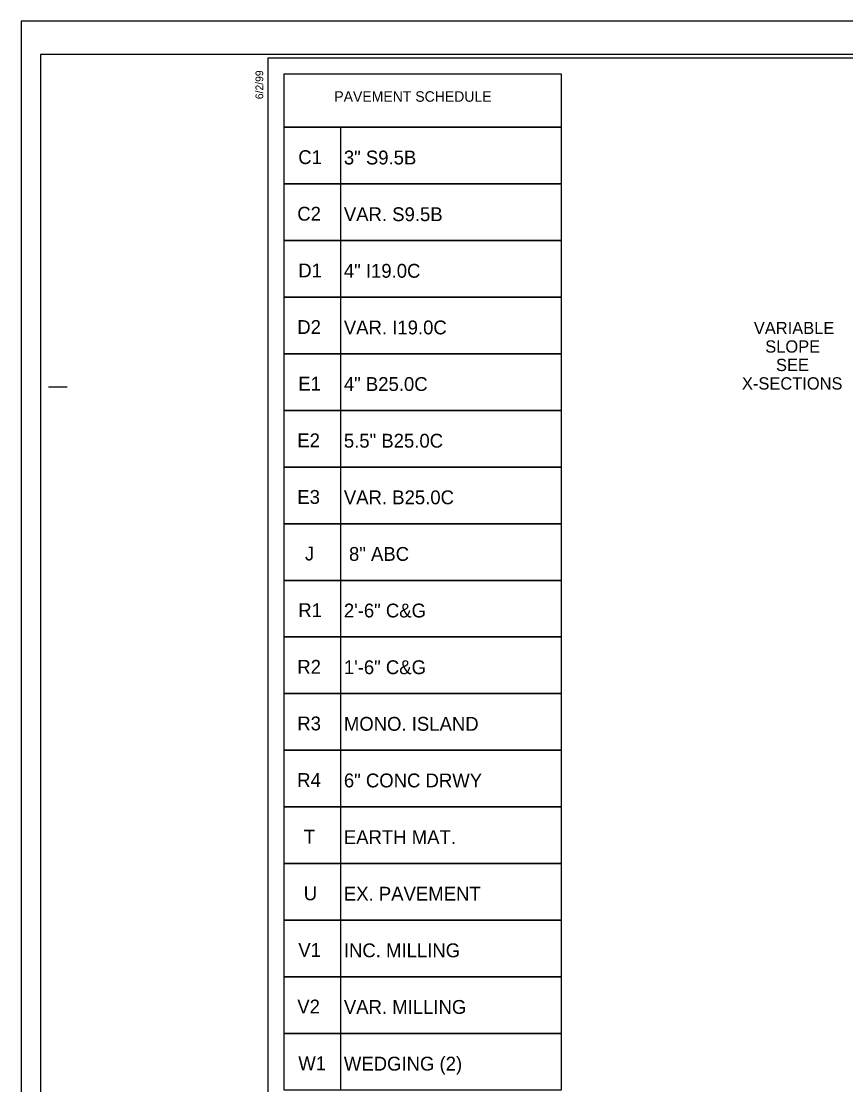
# Model space of a CAD drawing. Extents: x 3025871 to 3026431, y 707165 to 707825.
# Drawn here: x 3026022 to 3026105.8, y 707279.4 to 707387.4 of the extents above; entities that cross this region are included whole.
import ezdxf

# ---------------------------------------------------------------- set-up
doc = ezdxf.new("R2010")
doc.units = 0
for name, color, linetype in [('Default', 7, 'Continuous'), ('Old_Level_39', 7, 'Continuous'), ('Prop Drainage Structure Junction Box with Slab Lid TB 840 34 CELL', 7, 'Continuous'), ('Sheet Cutting Line CELL', 7, 'Continuous'), ('Typical ID Circle CELL', 7, 'Continuous'), ('Typical Terminator CELL', 7, 'Continuous')]:
    doc.layers.add(name, color=color, linetype=linetype)

msp = doc.modelspace()

# ---------------------------------------------------------------- linework, layer by layer
at = {"layer": 'Default'}
msp.add_lwpolyline([(3026048.72, 707382.05), (3026076.85, 707382.05), (3026076.85, 707376.61), (3026048.72, 707376.61)], close=True, dxfattribs=at)
at = {"layer": 'Old_Level_39'}
msp.add_lwpolyline([(3026273.95, 707384.02), (3026023.97, 707384.02), (3026023.97, 707225.75), (3026273.95, 707225.75)], close=True, dxfattribs=at)
at = {"layer": 'Sheet Cutting Line CELL'}
msp.add_line((3026024.8, 707350.26), (3026026.67, 707350.26), dxfattribs=at)
msp.add_lwpolyline([(3026272.07, 707383.63), (3026047.07, 707383.63), (3026047.07, 707226.13), (3026272.07, 707226.13)], close=True, dxfattribs=at)
at = {"layer": 'Typical ID Circle CELL'}
for points in [[(3026054.48, 707370.86), (3026048.72, 707370.86), (3026048.72, 707376.61), (3026076.85, 707376.61), (3026076.85, 707370.86), (3026054.48, 707370.86), (3026054.48, 707376.61)], [(3026054.48, 707365.1), (3026048.72, 707365.1), (3026048.72, 707370.86), (3026076.85, 707370.86), (3026076.85, 707365.1), (3026054.48, 707365.1), (3026054.48, 707370.86)], [(3026054.48, 707359.35), (3026048.72, 707359.35), (3026048.72, 707365.1), (3026076.85, 707365.1), (3026076.85, 707359.35), (3026054.48, 707359.35), (3026054.48, 707365.1)], [(3026054.48, 707353.6), (3026048.72, 707353.6), (3026048.72, 707359.35), (3026076.85, 707359.35), (3026076.85, 707353.6), (3026054.48, 707353.6), (3026054.48, 707359.35)], [(3026054.48, 707347.85), (3026048.72, 707347.85), (3026048.72, 707353.6), (3026076.85, 707353.6), (3026076.85, 707347.85), (3026054.48, 707347.85), (3026054.48, 707353.6)], [(3026054.48, 707342.09), (3026048.72, 707342.09), (3026048.72, 707347.85), (3026076.85, 707347.85), (3026076.85, 707342.09), (3026054.48, 707342.09), (3026054.48, 707347.85)], [(3026054.48, 707336.34), (3026048.72, 707336.34), (3026048.72, 707342.09), (3026076.85, 707342.09), (3026076.85, 707336.34), (3026054.48, 707336.34), (3026054.48, 707342.09)], [(3026054.48, 707330.59), (3026048.72, 707330.59), (3026048.72, 707336.34), (3026076.85, 707336.34), (3026076.85, 707330.59), (3026054.48, 707330.59), (3026054.48, 707336.34)], [(3026054.48, 707324.84), (3026048.72, 707324.84), (3026048.72, 707330.59), (3026076.85, 707330.59), (3026076.85, 707324.84), (3026054.48, 707324.84), (3026054.48, 707330.59)], [(3026054.48, 707319.08), (3026048.72, 707319.08), (3026048.72, 707324.84), (3026076.85, 707324.84), (3026076.85, 707319.08), (3026054.48, 707319.08), (3026054.48, 707324.84)], [(3026054.48, 707313.33), (3026048.72, 707313.33), (3026048.72, 707319.08), (3026076.85, 707319.08), (3026076.85, 707313.33), (3026054.48, 707313.33), (3026054.48, 707319.08)], [(3026054.48, 707307.58), (3026048.72, 707307.58), (3026048.72, 707313.33), (3026076.85, 707313.33), (3026076.85, 707307.58), (3026054.48, 707307.58), (3026054.48, 707313.33)], [(3026054.48, 707301.82), (3026048.72, 707301.82), (3026048.72, 707307.58), (3026076.85, 707307.58), (3026076.85, 707301.82), (3026054.48, 707301.82), (3026054.48, 707307.58)], [(3026054.48, 707296.07), (3026048.72, 707296.07), (3026048.72, 707301.82), (3026076.85, 707301.82), (3026076.85, 707296.07), (3026054.48, 707296.07), (3026054.48, 707301.82)], [(3026054.48, 707290.32), (3026048.72, 707290.32), (3026048.72, 707296.07), (3026076.85, 707296.07), (3026076.85, 707290.32), (3026054.48, 707290.32), (3026054.48, 707296.07)], [(3026054.48, 707284.57), (3026048.72, 707284.57), (3026048.72, 707290.32), (3026076.85, 707290.32), (3026076.85, 707284.57), (3026054.48, 707284.57), (3026054.48, 707290.32)], [(3026054.48, 707278.81), (3026048.72, 707278.81), (3026048.72, 707284.57), (3026076.85, 707284.57), (3026076.85, 707278.81), (3026054.48, 707278.81), (3026054.48, 707284.57)]]:
    msp.add_lwpolyline(points, dxfattribs=at)
at = {"layer": 'Typical Terminator CELL'}
msp.add_lwpolyline([(3026274.62, 707387.38), (3026022.02, 707387.38), (3026022.02, 707222.38), (3026274.62, 707222.38)], close=True, dxfattribs=at)

# ---------------------------------------------------------------- texts
at = {"layer": 'Default'}
msp.add_text('PAVEMENT SCHEDULE', height=1.0642, dxfattribs=at).set_placement((3026053.82, 707379.21))
at = {"layer": 'Prop Drainage Structure Junction Box with Slab Lid TB 840 34 CELL'}
for s, p in [('VARIABLE', (3026096.43, 707355.6)), ('SLOPE', (3026097.59, 707353.72)), ('SEE', (3026098.68, 707351.85)), ('X-SECTIONS', (3026095.22, 707349.97))]:
    msp.add_text(s, height=1.25, dxfattribs=at).set_placement(p)
at = {"layer": 'Sheet Cutting Line CELL'}
msp.add_text('6/2/99', height=0.787, rotation=90, dxfattribs=at).set_placement((3026046.6, 707379.47))
at = {"layer": 'Typical ID Circle CELL'}
for s, height, p in [('C1', 1.406, (3026050.16, 707372.88)), ('3" S9.5B', 1.406, (3026054.79, 707372.84)), ('C2', 1.406, (3026050.06, 707367.13)), ('VAR. S9.5B', 1.406, (3026054.79, 707367.08)), ('D1', 1.406, (3026050.16, 707361.37)), ('4" I19.0C', 1.406, (3026054.79, 707361.33)), ('D2', 1.406, (3026050.06, 707355.62)), ('VAR. I19.0C', 1.4062, (3026054.79, 707355.58)), ('E1', 1.406, (3026050.16, 707349.87)), ('4" B25.0C', 1.406, (3026054.79, 707349.83)), ('E2', 1.406, (3026050.06, 707344.11)), ('5.5" B25.0C', 1.4062, (3026054.79, 707344.07)), ('E3', 1.406, (3026050.06, 707338.36)), ('VAR. B25.0C', 1.4062, (3026054.79, 707338.32)), ('R1', 1.406, (3026050.16, 707326.86)), ('2\'-6" C&G', 1.406, (3026054.79, 707326.82)), ('R2', 1.406, (3026050.06, 707321.1)), ('1\'-6" C&G', 1.406, (3026054.79, 707321.06)), ('R3', 1.406, (3026050.06, 707315.35)), ('MONO. ISLAND', 1.4062, (3026054.79, 707315.31)), ('R4', 1.406, (3026050.05, 707309.6)), ('6" CONC DRWY', 1.4062, (3026054.79, 707309.56)), ('T', 1.41, (3026050.71, 707303.84)), ('EARTH MAT.', 1.406, (3026054.79, 707303.8)), ('U', 1.41, (3026050.71, 707298.09)), ('EX. PAVEMENT', 1.4062, (3026054.79, 707298.05)), ('V1', 1.406, (3026050.16, 707292.34)), ('INC. MILLING', 1.4062, (3026054.79, 707292.3)), ('V2', 1.406, (3026050.06, 707286.59)), ('VAR. MILLING', 1.4062, (3026054.79, 707286.55)), ('W1', 1.406, (3026050.16, 707280.83)), ('WEDGING (2)', 1.4062, (3026054.79, 707280.79))]:
    msp.add_text(s, height=height, dxfattribs=at).set_placement(p)
for s, height, p in [('J', 1.41, (3026050.83, 707332.61)), (' 8" ABC', 1.406, (3026054.79, 707332.57))]:
    msp.add_text(s, height=height, rotation=360, dxfattribs=at).set_placement(p)

doc.saveas('drawing.dxf')
